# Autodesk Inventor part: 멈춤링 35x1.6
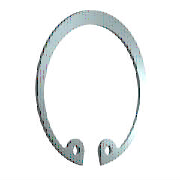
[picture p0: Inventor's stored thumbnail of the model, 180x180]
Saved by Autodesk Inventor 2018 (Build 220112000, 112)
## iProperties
IsCustomPart: 1
Created: 2015-09
Part Number: 멈춤링 35x1.6
Material: 강철, 연강
Description: 리테이닝 링(C형)
Document SubType Name: Modeling
Standard: KS B 1336
Designer: mduedu
Standards Organization: KS
Language: ko-KR
Size Designation: 35x1.6
Categories: <MemberInstance><Categories><Category DisplayName="샤프트 부품" InternalName="7f7aeb1f-a693-4053-b835-cee3144e0d98" Mnemonic="SHFT"><Category DisplayName="써클립" Inter
Density: 7.86 g/cm^3
Mass: 3.5371 g
Surface Area: 9.09651 cm^2
Volume: 0.450013 cm^3
Appearance: 파란색 - 벽 페인트 - 광택
Author: mduedu
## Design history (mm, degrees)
sketch "스케치1"
  geometry: L1 (0, 15.113)-(0, -73.177) reference; L2 (-45.5, 0)-(45.5, 0) reference; L3 (-4.964, 1)-(1.502, 1); L4 (0, -2.5)-(-5.307, -2.5); L5 (0, -17.5)-(-8.583, -33.888); L6 (-8.583, -33.888)-(-21.772, -26.981); L7 (-7.377, -31.585)-(-17.631, -26.214); L8 (-5.162, -32.745)-(-6.29, -34.898); L9 (5.162, -32.745)-(6.29, -34.898); C1 r 1.25 at (-7.377, -31.585); C2 r 1.25 at (7.377, -31.585); A1 r 15.875 centre (0, -18.375) between (11.82, -28.972) and (-11.82, -28.972); A2 r 18.5 centre (0, -17.5) between (6.29, -34.898) and (-6.29, -34.898); A3 r 2.5 centre (-7.377, -31.585) between (-5.162, -32.745) and (-8.668, -29.444); A4 r 2.5 centre (-9.959, -27.303) between (-11.82, -28.972) and (-8.668, -29.444); A5 r 2.5 centre (9.959, -27.303) between (8.668, -29.444) and (11.82, -28.972); A6 r 2.5 centre (7.377, -31.585) between (8.668, -29.444) and (5.162, -32.745); 3 further points
  constraints: 15 point on circle, 14 end point, 9 symmetric about line, 8 centre point, 6 tangent, 4 coincident, 4 point on line, 3 perpendicular, 1 parallel, 4 other
  dimensions: "d8" = 0.875 distance of A1.centre L5.start (= 0.25 x SRB1); "d38" = 3.5 distance between parallel lines of L4 L3 (= SRB1); "d39" = 17.5 distance from line of L5.start L2 (= 0.5 x WD); "d43" = 18.5 radius of A2 (= 0.5 x ND); "d45" = 2.6 distance between parallel lines of L7 L6 (= 0.5 x SRB2); "d46" = 2.5 radius of A4 (= SD5); "d47" = 6.29 distance from line of L1 L8.end (= 0.17 x ND); "d48" = 2.5 diameter of C1 (= SD5); "d49" = 2.5 radius of A3 (= SD5)
extrude "본체" new body sketch "스케치1" distance "d2" = 1.6 (= SD); taper "d3" = 0 deg
workaxis "Work Axis1"
workaxis "Work Axis2"
workplane "Work Plane1"
body "Solid1"
other parameters: "WD" = 35 [user parameter; used in 3 equation terms], "SD" = 1.6 [user parameter; used in 1 equation term], "SRB1" = 3.5 [user parameter; used in 2 equation terms], "ND" = 37 [user parameter; used in 2 equation terms], "SRB2" = 5.2 [user parameter; used in 1 equation term], "SD5" = 2.5 [user parameter; used in 3 equation terms], "d50" = 0, "d51" = 0, "d52" = 0, "d53" = 0, "WDMIN" = 34 [user parameter], "SD6" = 37.8 [user parameter], "WDMAX" = 35 (= WD) [user parameter], "NND" = 35 (= WD) [user parameter]
